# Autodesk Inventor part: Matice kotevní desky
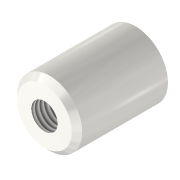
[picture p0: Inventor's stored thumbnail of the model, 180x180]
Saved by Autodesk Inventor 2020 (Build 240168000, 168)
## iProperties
Created: 2025-03
Part Number: Matice kotevní desky
Material: Ocel
Document SubType Name: Modeling
Designer: doma
Density: 7.85 g/cm^3
Appearance: Ocel
Author: doma
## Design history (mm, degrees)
sketch "Náčrt1"
  geometry: C1 r 12.5 at (0, 0); 1 further point
  constraints: 1 centre point, 1 coincident
  dimensions: "d0" = 25 diameter of C1
extrude "Vysunutí1" new body sketch "Náčrt1" distance "d1" = 35; taper "d2" = 0 deg
sketch "Náčrt2"
  geometry: 2 further points
hole "Díra1" sketch "Náčrt2" at (0, 0) diameter "d3" = 10.106; stored, may be unused: countersink angle "d7" = 90 deg, drill point angle "d9" = 118 deg; dims "d4" = 24, "d5" = 4, "d6" = 2, "d8" = 32.3
chamfer "Zkosení1" distance "d10" = 2; stored, may be unused: second distance "d11" = 2, angle "d12" = 45 deg
node "Těleso1"
